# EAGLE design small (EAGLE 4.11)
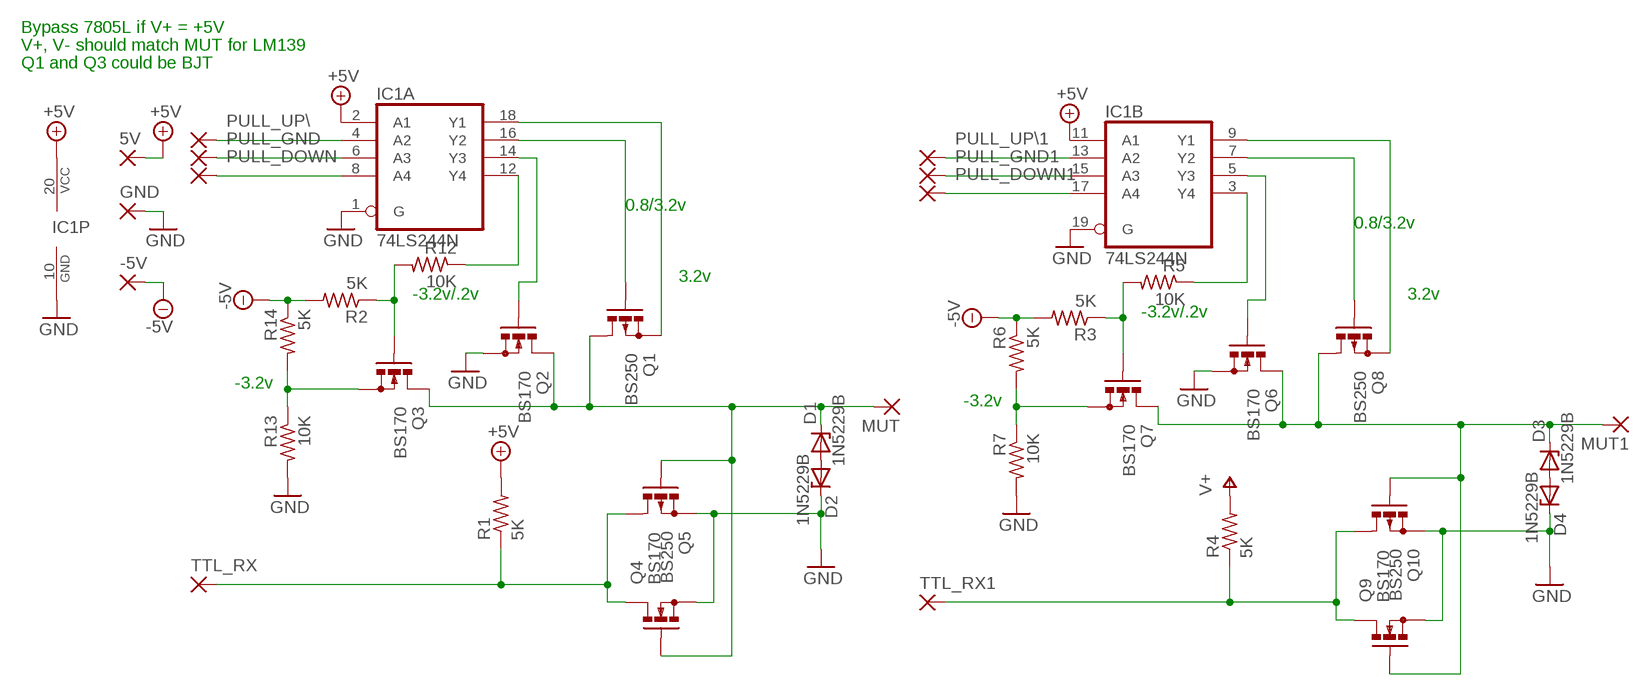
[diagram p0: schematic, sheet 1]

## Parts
5V  1,6/0,9  [1,6/0,9]
-5V  1,6/0,9  [1,6/0,9]
D1  1N5229B  ZENER-DIODEDO35Z10  [DO35Z10]
D2  1N5229B  ZENER-DIODEDO35Z10  [DO35Z10]
D3  1N5229B  ZENER-DIODEDO35Z10  [DO35Z10]
D4  1N5229B  ZENER-DIODEDO35Z10  [DO35Z10]
GND  1,6/0,9  [1,6/0,9]
IC1  74LS244N  [DIL20]
MUT  1,6/0,9  [1,6/0,9]
MUT1  1,6/0,9  [1,6/0,9]
PULL_DOWN  1,6/0,9  [1,6/0,9]
PULL_DOWN1  1,6/0,9  [1,6/0,9]
PULL_GND  1,6/0,9  [1,6/0,9]
PULL_GND1  1,6/0,9  [1,6/0,9]
PULL_UP\  1,6/0,9  [1,6/0,9]
PULL_UP\1  1,6/0,9  [1,6/0,9]
Q1  BS250  [SOT54E]
Q2  BS170  [SOT54E]
Q3  BS170  [SOT54E]
Q4  BS170  [SOT54E]
Q5  BS250  [SOT54E]
Q6  BS170  [SOT54E]
Q7  BS170  [SOT54E]
Q8  BS250  [SOT54E]
Q9  BS170  [SOT54E]
Q10  BS250  [SOT54E]
R1  5K  R-US_0207/10  [0207/10]
R2  5K  R-US_0207/10  [0207/10]
R3  5K  R-US_0207/10  [0207/10]
R4  5K  R-US_0207/10  [0207/10]
R5  10K  R-US_0207/10  [0207/10]
R6  5K  R-US_0207/10  [0207/10]
R7  10K  R-US_0207/10  [0207/10]
R12  10K  R-US_0207/10  [0207/10]
R13  10K  R-US_0207/10  [0207/10]
R14  5K  R-US_0207/10  [0207/10]
TTL_RX  1,6/0,9  [1,6/0,9]
TTL_RX1  1,6/0,9  [1,6/0,9]

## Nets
+5V: 5V.1(P) IC1.2(A:A1) IC1.11(B:A1) IC1.20(P:VCC) R1.2
-5V: -5V.1(P) R2.2 R3.2 R6.1 R14.1
GND: D2.C D4.C GND.1(P) IC1.1(A:G) IC1.10(P:GND) IC1.19(B:G) Q2.S Q4.S Q5.S Q6.S Q9.S Q10.S R7.2 R13.2
N$1: D1.C MUT.1(P) Q1.D Q2.D Q3.D Q4.G Q5.G
N$2: Q3.G R2.1 R12.2
N$3: IC1.6(A:A3) PULL_GND.1(P)
N$4: IC1.8(A:A4) PULL_DOWN.1(P)
N$5: IC1.18(A:Y1) Q1.S
N$6: IC1.16(A:Y2) Q1.G
N$7: D1.A D2.A
N$8: Q4.D Q5.D R1.1 TTL_RX.1(P)
N$9: IC1.12(A:Y4) R12.1
N$10: IC1.4(A:A2) PULL_UP\.1(P)
N$11: IC1.14(A:Y3) Q2.G
N$12: IC1.15(B:A3) PULL_GND1.1(P)
N$13: IC1.17(B:A4) PULL_DOWN1.1(P)
N$14: Q7.G R3.1 R5.2
N$15: Q7.S R6.2 R7.1
N$16: Q3.S R13.1 R14.2
N$17: IC1.9(B:Y1) Q8.S
N$18: D3.C MUT1.1(P) Q6.D Q7.D Q8.D Q9.G Q10.G
N$19: IC1.13(B:A2) PULL_UP\1.1(P)
N$20: D3.A D4.A
N$21: Q9.D Q10.D R4.1 TTL_RX1.1(P)
N$22: IC1.7(B:Y2) Q8.G
N$23: IC1.3(B:Y4) R5.1
N$24: IC1.5(B:Y3) Q6.G
V+: R4.2

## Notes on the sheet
- Bypass 7805L if V+ = +5V
- V+, V- should match MUT for LM139
- Q1 and Q3 could be BJT
- 0.8/3.2v
- 0.8/3.2v
- 3.2v
- -3.2v/.2v | 3.2v
- -3.2v/.2v
- -3.2v
- -3.2v

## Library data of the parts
5V -5V GND MUT MUT1 PULL_DOWN PULL_DOWN1 PULL_GND PULL_GND1 PULL_UP\ PULL_UP\1 TTL_RX TTL_RX1 = wirepad:1,6/0,9: THROUGH-HOLE PAD
D1-D4 = diode:ZENER-DIODE: Z-Diode
IC1 = 74xx-jameco:74*244: Octal BUFFER and LINE DRIVER, 3-state
Q1 Q5 Q8 Q10 = transistor-small-signal:BS250: P-CHANNEL MOS FET
Q2-Q4 Q6 Q7 Q9 = transistor-small-signal:BS170: N-CHANNEL MOS FET
R1-R7 R12-R14 = rcl:R-US_: RESISTOR, American symbol

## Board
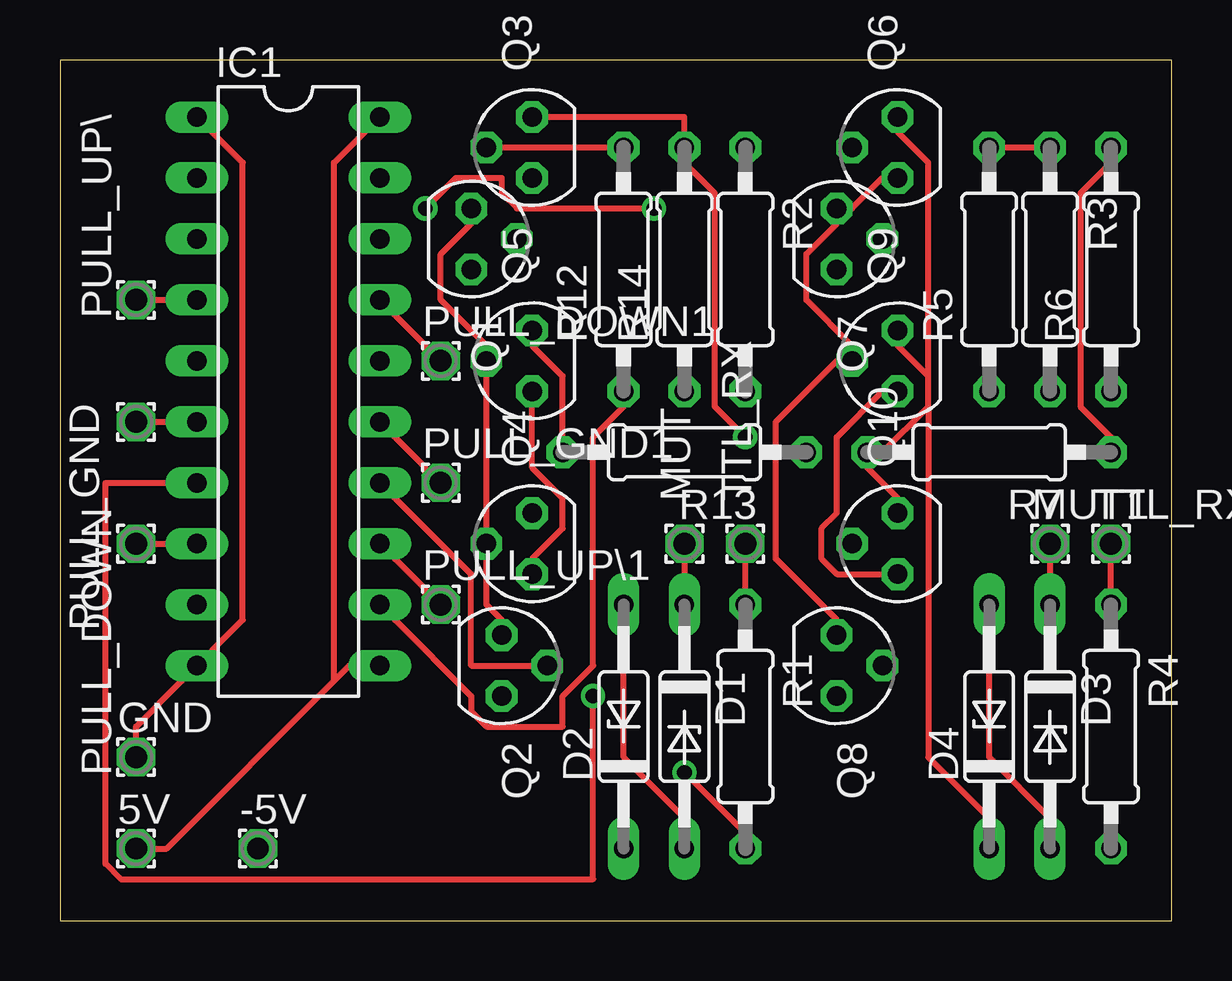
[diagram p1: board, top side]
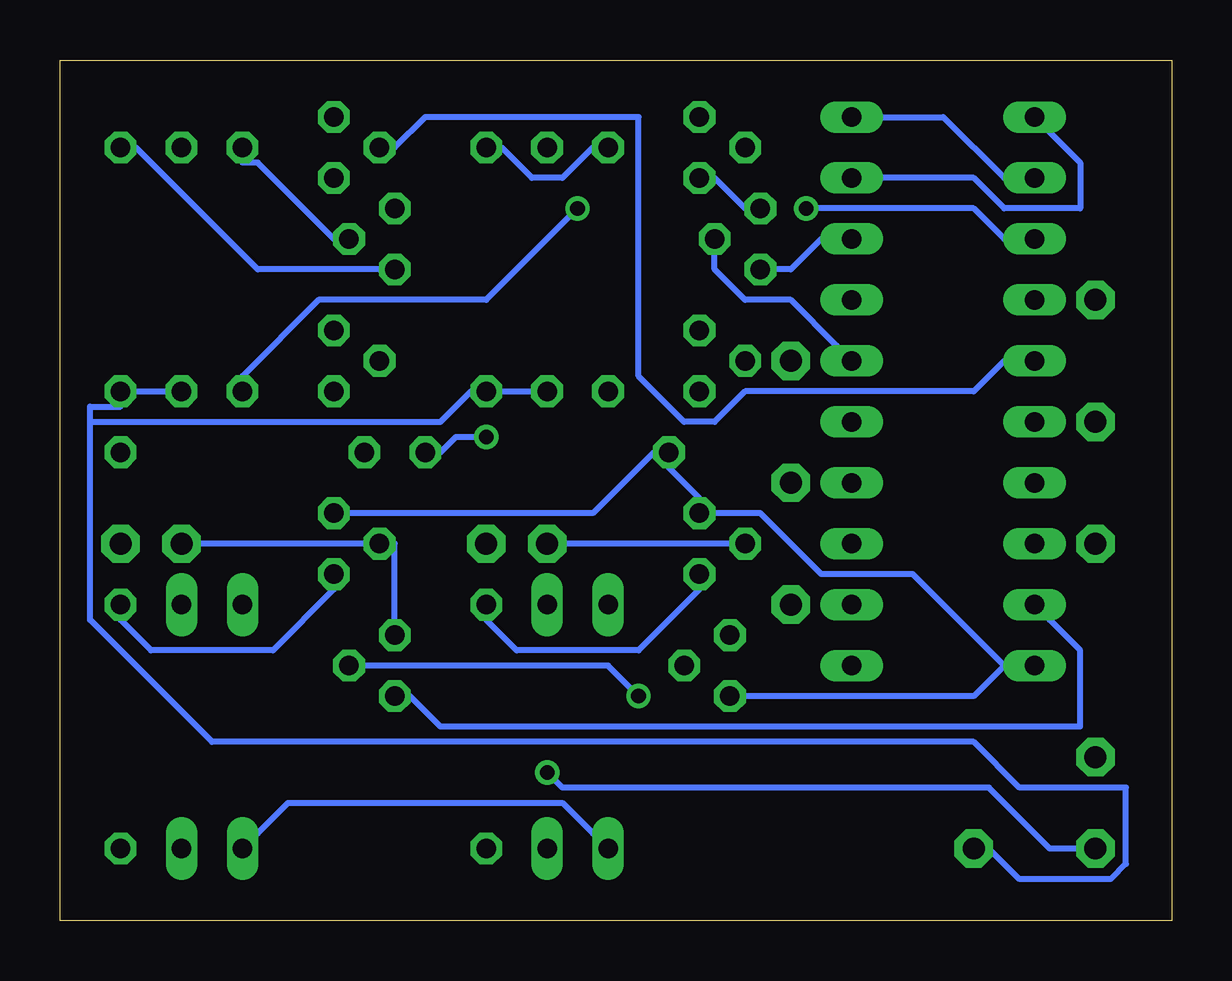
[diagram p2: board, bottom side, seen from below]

Size 46.34 x 35.87 mm. Coordinates in mm from the lower left corner, seen from the top.
Outline: 0,0 46.34,0 46.34,35.87 0,35.87 0,0
Copper layers (1*16): Top 0.035mm / dielectric 1.5mm / Bottom 0.035mm
Design rules "default": minimum track width 10mil, minimum drill 24mil, track to track 8mil, track to pad 8mil, pad to pad 8mil, via to via 8mil, smd to smd 8mil, copper to edge 40mil, drill to drill 8mil, minimum pad ring 10mil, minimum via ring 8mil, stop-mask expansion 4mil, vias tented up to drill 0mil, thermal gap 10mil

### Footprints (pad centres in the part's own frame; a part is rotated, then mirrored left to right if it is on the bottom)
1,6/0,9 = drill 0.914 pad 1.6 octagon: 1 0,0
DO35Z10 = drill 0.813 long: A 5.08,0; C -5.08,0
DIL20 = drill 0.813 long: 1 -11.43,-3.81; 2 -8.89,-3.81; 3 -6.35,-3.81; 4 -3.81,-3.81; 5 -1.27,-3.81; 6 1.27,-3.81; 7 3.81,-3.81; 8 6.35,-3.81; 9 8.89,-3.81; 10 11.43,-3.81; 11 11.43,3.81; 12 8.89,3.81; 13 6.35,3.81; 14 3.81,3.81; 15 1.27,3.81; 16 -1.27,3.81; 17 -3.81,3.81; 18 -6.35,3.81; 19 -8.89,3.81; 20 -11.43,3.81
SOT54E = drill 0.813 octagon: D -1.27,0; G 0,1.905; S 1.27,0
0207/10 = drill 0.813 octagon: 1 -5.08,0; 2 5.08,0

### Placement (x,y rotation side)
5V  3.17,3.01 0 top
-5V  8.25,3.01 0 top
D1  26.03,8.09 270 top
D2  23.49,8.09 90 top
D3  41.27,8.09 270 top
D4  38.73,8.09 90 top
GND  3.17,6.82 0 top
IC1  9.52,22.06 270 top
MUT  26.03,15.71 90 top
MUT1  41.27,15.71 0 top
PULL_DOWN  3.17,15.71 270 top
PULL_DOWN1  15.87,23.33 0 top
PULL_GND  3.17,20.79 180 top
PULL_GND1  15.87,18.25 0 top
PULL_UP\  3.17,25.87 90 top
PULL_UP\1  15.87,13.17 0 top
Q1  17.14,28.41 270 top
Q2  18.41,10.63 270 top
Q3  19.68,32.22 90 top
Q4  19.68,15.71 90 top
Q5  19.68,23.33 90 top
Q6  34.92,32.22 90 top
Q7  32.38,28.41 270 top
Q8  32.38,10.63 270 top
Q9  34.92,23.33 90 top
Q10  34.92,15.71 90 top
R1  28.57,8.09 270 top
R2  28.57,27.14 270 top
R3  41.27,27.14 270 top
R4  43.81,8.09 270 top
R5  38.73,27.14 90 top
R6  43.81,27.14 90 top
R7  38.73,19.52 180 top
R12  23.49,27.14 90 top
R13  26.03,19.52 180 top
R14  26.03,27.14 90 top
TTL_RX  28.57,15.71 90 top
TTL_RX1  43.81,15.71 0 top

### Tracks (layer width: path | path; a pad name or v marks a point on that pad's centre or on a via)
+5V  (via drill 0.61)
  Top 0.254: 11.43,10 4.44,3.01 3.8,3.01 5V.1 | 11.43,10 12.06,10.63 IC1.11 | v26.03,6.18 28.57,3.64 R1.2 | 11.43,10 11.43,31.58 12.7,32.85 IC1.20
  Bottom 0.254: IC1.2 6.98,30.95 9.52,33.49 12.06,33.49 IC1.20 | v26.03,6.18 25.39,5.55 7.62,5.55 5.08,3.01 3.8,3.01 5V.1
-5V
  Bottom 0.254: R14.1 26.66,22.06 27.93,22.06 R2.2 29.2,22.06 30.47,20.79 45.08,20.79 | R3.2 41.91,22.06 43.18,22.06 R6.1 43.81,21.42 45.08,21.42 45.08,20.79 | 45.08,20.79 45.08,12.54 40,7.46 8.25,7.46 6.34,5.55 1.9,5.55 1.9,2.38 2.54,1.74 6.34,1.74 7.62,3.01 -5V.1
GND
  Top 0.254: GND.1 3.17,7.46 3.17,8.09 5.08,10 IC1.10 6.34,11.27 7.62,12.54 7.62,31.58 6.34,32.85 IC1.1 | Q5.S 19.68,23.96 20.95,22.7 20.95,20.15 R13.2 | Q10.S 34.92,17.61 33.65,18.88 R7.2 34.29,19.52 36.19,21.42 | 36.19,22.7 34.92,23.96 Q9.S | 36.19,21.42 36.19,22.7 | 36.19,22.7 36.19,31.58 34.92,32.85 Q6.S | 36.19,21.42 36.19,6.82 38.73,4.28 D4.C
  Bottom 0.254: IC1.1 5.08,32.85 3.8,31.58 3.8,29.68 6.98,29.68 8.25,30.95 12.06,30.95 IC1.19 | 6.98,10.63 8.25,9.36 17.77,9.36 Q2.S | 6.98,10.63 IC1.10 6.98,10.63 | D2.C 24.12,3.64 25.39,4.92 36.83,4.92 38.1,3.64 D4.C | Q10.S 34.29,16.98 24.12,16.98 21.58,19.52 R13.2 20.95,18.88 19.68,17.61 Q4.S 19.04,16.98 17.14,16.98 14.6,14.44 10.79,14.44 6.98,10.63
N$1
  Top 0.254: D1.C 26.03,14.44 26.03,15.08 MUT.1 | Q2.D 18.41,12.54 17.77,13.17 17.77,15.08 Q4.G 17.77,16.34 17.77,22.7 Q5.G 17.77,23.96 15.87,25.87 15.87,27.77 17.14,29.04 Q1.D
  Bottom 0.254: Q1.D 17.77,29.68 19.04,30.95 Q3.D | MUT.1 25.39,15.71 18.41,15.71 Q4.G
N$2
  Top 0.254: Q3.G 18.41,32.22 22.86,32.22 R12.2
  Bottom 0.254: R2.1 27.93,32.22 26.66,30.95 25.39,30.95 24.12,32.22 R12.2
N$3
  Top 0.254: IC1.6 4.44,20.79 3.8,20.79 PULL_GND.1
N$4
  Top 0.254: IC1.8 4.44,15.71 3.8,15.71 PULL_DOWN.1
N$5
  Bottom 0.254: IC1.18 14.6,28.41 15.87,27.14 16.5,27.14 Q1.S
N$6
  Bottom 0.254: IC1.16 13.97,23.96 15.87,25.87 17.77,25.87 19.04,27.14 19.04,27.77 Q1.G
N$7
  Top 0.254: D1.A 26.03,4.28 23.49,6.82 23.49,11.9 D2.A
N$8
  Top 0.254: R1.1 28.57,13.81 28.57,15.08 TTL_RX.1 | Q4.D 19.68,15.08 20.95,16.34 20.95,17.61 19.68,18.88 19.68,21.42 Q5.D
  Bottom 0.254: R1.1 28.57,12.54 27.3,11.27 22.22,11.27 19.68,13.81 Q4.D
N$9
  Top 0.254: IC1.12 13.97,12.54 17.14,9.36 17.14,8.73 17.77,8.09 20.95,8.09 20.95,9.36 22.22,10.63 22.22,20.15 23.49,21.42 R12.1
N$10
  Top 0.254: IC1.4 4.44,25.87 3.8,25.87 PULL_UP\.1
N$11
  Top 0.254: Q2.G 19.68,10.63 17.14,10.63 17.14,14.44 13.97,17.61 IC1.14
N$12
  Top 0.254: IC1.15 13.97,20.15 15.24,18.88 15.24,18.25 PULL_GND1.1
N$13
  Top 0.254: IC1.17 13.97,25.23 15.24,23.96 15.24,23.33 PULL_DOWN1.1
N$14
  Top 0.254: R3.1 40.64,32.22 39.37,32.22 R5.2
  Bottom 0.254: Q7.G 34.92,28.41 38.1,31.58 38.73,31.58 R5.2
N$15
  Top 0.254: R7.1 43.81,20.15 42.54,21.42 42.54,30.31 43.81,31.58 R6.2
  Bottom 0.254: Q7.S 33.02,27.14 38.1,27.14 43.18,32.22 R6.2
N$16  (via drill 0.61)
  Top 0.254: v28.57,20.15 27.3,21.42 27.3,30.31 26.03,31.58 R14.2 26.03,32.85 26.03,33.49 20.31,33.49 Q3.S
  Bottom 0.254: v28.57,20.15 29.84,20.15 30.47,19.52 R13.1
N$17
  Bottom 0.254: IC1.9 5.08,12.54 3.8,11.27 3.8,8.09 30.47,8.09 31.74,9.36 Q8.S
N$18
  Top 0.254: Q6.D 34.29,30.95 33.02,29.68 Q7.D 32.38,29.04 31.11,27.77 31.11,25.87 33.02,23.96 Q9.G 32.38,23.33 29.84,20.79 29.84,15.08 32.38,12.54 Q8.D | D3.C 41.27,14.44 41.27,15.08 MUT1.1
  Bottom 0.254: Q8.D 32.38,12.54 32.38,15.71 Q10.G 33.65,15.71 40.64,15.71 MUT1.1
N$19
  Top 0.254: IC1.13 13.97,15.08 15.24,13.81 15.24,13.17 PULL_UP\1.1
N$20
  Top 0.254: D3.A 41.27,4.28 38.73,6.82 38.73,11.9 D4.A
N$21
  Top 0.254: Q9.D 34.29,22.06 32.38,20.15 32.38,16.98 31.74,16.34 31.74,15.08 32.38,14.44 34.29,14.44 Q10.D | TTL_RX1.1 43.81,15.08 43.81,13.81 R4.1
  Bottom 0.254: Q10.D 34.92,13.81 37.46,11.27 42.54,11.27 43.81,12.54 R4.1
N$22  (via drill 0.61)
  Top 0.254: v22.22,9.36 22.22,1.74 2.54,1.74 1.9,2.38 1.9,18.25 4.44,18.25 IC1.7
  Bottom 0.254: v22.22,9.36 23.49,10.63 33.65,10.63 Q8.G
N$23  (via drill 0.61)
  Top 0.254: v15.24,29.68 16.5,30.95 18.41,30.95 18.41,30.31 19.04,29.68 v24.76,29.68
  Bottom 0.254: v15.24,29.68 8.25,29.68 6.98,28.41 IC1.3 | v24.76,29.68 28.57,25.87 35.55,25.87 38.73,22.7 R5.1
N$24
  Bottom 0.254: IC1.5 6.98,23.33 8.25,22.06 17.77,22.06 19.04,20.79 20.31,20.79 22.22,22.7 22.22,33.49 31.11,33.49 32.38,32.22 Q6.G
